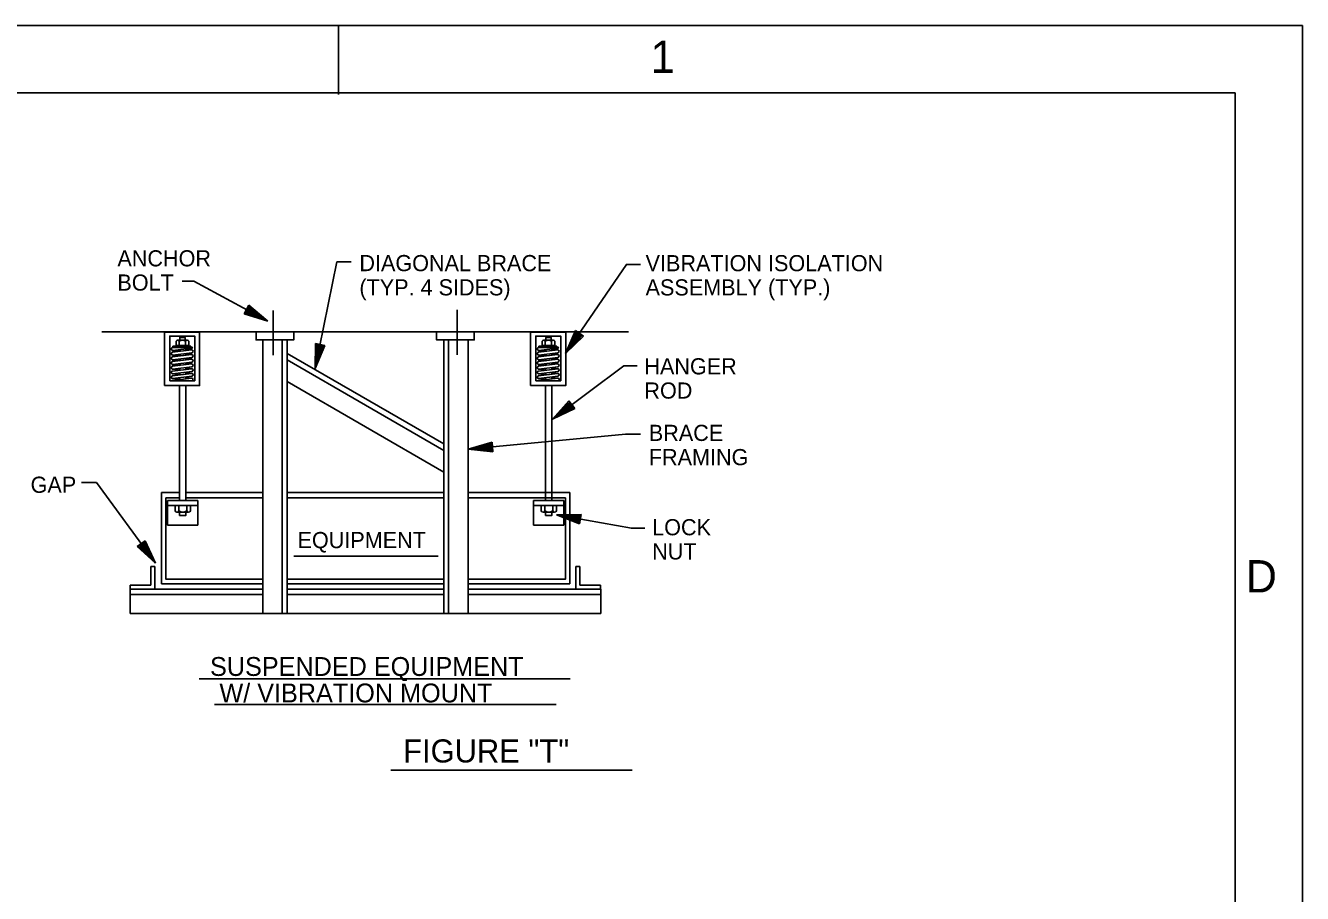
# Model space of a CAD drawing. Extents: x 9999.96 to 10005.26, y 9999.88 to 10002.38.
# Drawn here: x 10002.67 to 10003.46, y 10001.847 to 10002.385 of the extents above; entities that cross this region are included whole.
import ezdxf

# ---------------------------------------------------------------- set-up
doc = ezdxf.new("R2010")
doc.units = 0
doc.layers.add('Level 1', color=7, linetype='Continuous')
doc.layers.add('Level 2', color=7, linetype='Continuous')

msp = doc.modelspace()

# ---------------------------------------------------------------- linework, layer by layer
at = {"layer": 'Level 1'}
for p, q in [((9999.96033, 10002.38453), (10003.46033, 10002.38453)), ((10002.8635, 10002.38453), (10002.8635, 10002.34186)), ((10003.46033, 10002.38453), (10003.46033, 9999.88453)), ((10000.127, 10002.34286), (10003.41867, 10002.34286)), ((10003.41867, 10002.34286), (10003.41867, 9999.9262))]:
    msp.add_line(p, q, dxfattribs=at)
at = {"layer": 'Level 2'}
for p, q in [((10002.80502, 10002.20613), (10002.8079, 10002.21143)), ((10002.8197, 10002.20163), (10002.80577, 10002.20755)), ((10002.8197, 10002.20163), (10002.8061, 10002.20814)), ((10002.80643, 10002.20876), (10002.8197, 10002.20163)), ((10002.8197, 10002.20163), (10002.80679, 10002.20942)), ((10002.8197, 10002.20163), (10002.80714, 10002.21008)), ((10002.8197, 10002.20163), (10002.80749, 10002.21071)), ((10002.8079, 10002.21143), (10002.8197, 10002.20163)), ((10002.82292, 10002.18049), (10002.82292, 10002.20824)), ((10002.93701, 10002.18075), (10002.93701, 10002.2085)), ((10002.80502, 10002.20613), (10002.8197, 10002.20163)), ((10002.8197, 10002.20163), (10002.80539, 10002.2068)), ((10002.71686, 10002.19493), (10003.04293, 10002.19493)), ((10003.0101, 10002.19567), (10003.0041, 10002.18154)), ((10003.0041, 10002.18154), (10003.01074, 10002.19524)), ((10003.0041, 10002.18154), (10003.01145, 10002.19478)), ((10003.0041, 10002.18154), (10003.01199, 10002.19439)), ((10003.01257, 10002.194), (10003.0041, 10002.18154)), ((10003.0041, 10002.18154), (10003.0132, 10002.19356)), ((10003.0041, 10002.18154), (10003.01381, 10002.19316)), ((10003.0041, 10002.18154), (10003.01441, 10002.19274)), ((10003.01508, 10002.19226), (10003.0041, 10002.18154)), ((10003.0101, 10002.19567), (10003.01508, 10002.19226)), ((10002.76067, 10002.18524), (10002.77322, 10002.18524)), ((10002.76068, 10002.18232), (10002.77251, 10002.18378)), ((10002.76084, 10002.18346), (10002.77268, 10002.18491)), ((10002.77209, 10002.18606), (10002.76091, 10002.18606)), ((10002.76091, 10002.18606), (10002.76091, 10002.18524)), ((10002.76286, 10002.18642), (10002.76286, 10002.18917)), ((10002.76286, 10002.18642), (10002.77076, 10002.18642)), ((10002.76385, 10002.18976), (10002.76977, 10002.18976)), ((10002.76482, 10002.18642), (10002.76482, 10002.18917)), ((10002.76506, 10002.18398), (10002.76506, 10002.18288)), ((10002.76879, 10002.18642), (10002.76879, 10002.18917)), ((10002.76899, 10002.18446), (10002.76899, 10002.18333)), ((10002.76899, 10002.18423), (10002.77259, 10002.18379)), ((10002.77076, 10002.18642), (10002.77076, 10002.18915)), ((10002.77209, 10002.18606), (10002.77209, 10002.18524)), ((10002.81652, 10002.02061), (10002.81652, 10002.1899)), ((10002.82858, 10002.1899), (10002.82858, 10002.02061)), ((10002.83163, 10002.02061), (10002.83163, 10002.1899)), ((10002.84911, 10002.18763), (10002.84906, 10002.17227)), ((10002.84906, 10002.17227), (10002.84986, 10002.18747)), ((10002.84906, 10002.17227), (10002.8507, 10002.18732)), ((10002.84906, 10002.17227), (10002.85135, 10002.18717)), ((10002.85204, 10002.18704), (10002.84906, 10002.17227)), ((10002.84906, 10002.17227), (10002.85278, 10002.18688)), ((10002.84906, 10002.17227), (10002.85351, 10002.18674)), ((10002.84906, 10002.17227), (10002.85422, 10002.18658)), ((10002.85502, 10002.18642), (10002.84906, 10002.17227)), ((10002.84911, 10002.18763), (10002.85502, 10002.18642)), ((10002.92863, 10002.1899), (10002.92863, 10002.02061)), ((10002.93166, 10002.02061), (10002.93166, 10002.1899)), ((10002.94372, 10002.1899), (10002.94372, 10002.02061)), ((10002.98731, 10002.18524), (10002.99986, 10002.18524)), ((10002.98732, 10002.18232), (10002.99916, 10002.18378)), ((10002.98749, 10002.18346), (10002.99932, 10002.18491)), ((10002.99874, 10002.18606), (10002.98755, 10002.18606)), ((10002.98755, 10002.18606), (10002.98755, 10002.18524)), ((10002.98951, 10002.18642), (10002.98951, 10002.18917)), ((10002.98951, 10002.18642), (10002.99741, 10002.18642)), ((10002.9905, 10002.18976), (10002.99642, 10002.18976)), ((10002.99147, 10002.18642), (10002.99147, 10002.18917)), ((10002.99171, 10002.18398), (10002.99171, 10002.18288)), ((10002.99544, 10002.18642), (10002.99544, 10002.18917)), ((10002.99564, 10002.18446), (10002.99564, 10002.18333)), ((10002.99564, 10002.18423), (10002.99924, 10002.18379)), ((10002.99741, 10002.18642), (10002.99741, 10002.18915)), ((10002.99874, 10002.18606), (10002.99874, 10002.18524)), ((10002.76528, 10002.18289), (10002.76067, 10002.18346)), ((10002.76067, 10002.17942), (10002.7725, 10002.18086)), ((10002.76528, 10002.17706), (10002.76067, 10002.17764)), ((10002.76068, 10002.17651), (10002.77251, 10002.17795)), ((10002.76528, 10002.17999), (10002.76069, 10002.18053)), ((10002.76084, 10002.17765), (10002.77268, 10002.17908)), ((10002.76085, 10002.18054), (10002.77269, 10002.182)), ((10002.76085, 10002.17473), (10002.77269, 10002.17618)), ((10002.76506, 10002.18107), (10002.76506, 10002.17995)), ((10002.76506, 10002.17818), (10002.76506, 10002.17705)), ((10002.76899, 10002.18159), (10002.76899, 10002.18047)), ((10002.7727, 10002.18086), (10002.76899, 10002.18132)), ((10002.76899, 10002.17867), (10002.76899, 10002.1775)), ((10002.77268, 10002.17795), (10002.76899, 10002.17841)), ((10002.76899, 10002.17573), (10002.76899, 10002.1746)), ((10002.92863, 10002.1256), (10002.83163, 10002.1816)), ((10002.83163, 10002.17751), (10002.92863, 10002.12151)), ((10002.99193, 10002.18289), (10002.98731, 10002.18346)), ((10002.98731, 10002.17942), (10002.99915, 10002.18086)), ((10002.99193, 10002.17706), (10002.98731, 10002.17764)), ((10002.98732, 10002.17651), (10002.99916, 10002.17795)), ((10002.99193, 10002.17999), (10002.98733, 10002.18053)), ((10002.98749, 10002.17765), (10002.99932, 10002.17908)), ((10002.9875, 10002.18054), (10002.99933, 10002.182)), ((10002.9875, 10002.17473), (10002.99933, 10002.17618)), ((10002.99171, 10002.18107), (10002.99171, 10002.17995)), ((10002.99171, 10002.17818), (10002.99171, 10002.17705)), ((10002.99564, 10002.18159), (10002.99564, 10002.18047)), ((10002.99934, 10002.18086), (10002.99564, 10002.18132)), ((10002.99564, 10002.17867), (10002.99564, 10002.1775)), ((10002.99932, 10002.17795), (10002.99564, 10002.17841)), ((10002.99564, 10002.17573), (10002.99564, 10002.1746)), ((10002.76067, 10002.17359), (10002.7725, 10002.17504)), ((10002.76528, 10002.17124), (10002.76067, 10002.1718)), ((10002.76067, 10002.16777), (10002.7725, 10002.16921)), ((10002.76068, 10002.17068), (10002.77251, 10002.17213)), ((10002.76528, 10002.17416), (10002.76069, 10002.17472)), ((10002.76528, 10002.16833), (10002.76069, 10002.1689)), ((10002.76084, 10002.17181), (10002.77268, 10002.17326)), ((10002.76085, 10002.16891), (10002.77269, 10002.17035)), ((10002.76506, 10002.17528), (10002.76506, 10002.17413)), ((10002.76506, 10002.17239), (10002.76506, 10002.17123)), ((10002.76506, 10002.16946), (10002.76506, 10002.16832)), ((10002.7727, 10002.17504), (10002.76899, 10002.1755)), ((10002.76899, 10002.17283), (10002.76899, 10002.17171)), ((10002.77268, 10002.17213), (10002.76899, 10002.17258)), ((10002.76899, 10002.16991), (10002.76899, 10002.16878)), ((10002.7727, 10002.16921), (10002.76899, 10002.16968)), ((10002.98731, 10002.17359), (10002.99915, 10002.17504)), ((10002.99193, 10002.17124), (10002.98731, 10002.1718)), ((10002.98731, 10002.16777), (10002.99915, 10002.16921)), ((10002.98732, 10002.17068), (10002.99916, 10002.17213)), ((10002.99193, 10002.17416), (10002.98733, 10002.17472)), ((10002.99193, 10002.16833), (10002.98733, 10002.1689)), ((10002.98749, 10002.17181), (10002.99932, 10002.17326)), ((10002.9875, 10002.16891), (10002.99933, 10002.17035)), ((10002.99171, 10002.17528), (10002.99171, 10002.17413)), ((10002.99171, 10002.17239), (10002.99171, 10002.17123)), ((10002.99171, 10002.16946), (10002.99171, 10002.16832)), ((10002.99934, 10002.17504), (10002.99564, 10002.1755)), ((10002.99564, 10002.17283), (10002.99564, 10002.17171)), ((10002.99932, 10002.17213), (10002.99564, 10002.17258)), ((10002.99564, 10002.16991), (10002.99564, 10002.16878)), ((10002.99934, 10002.16921), (10002.99564, 10002.16968)), ((10002.75906, 10002.16466), (10002.77251, 10002.1663)), ((10002.76528, 10002.16542), (10002.76067, 10002.16598)), ((10002.76084, 10002.16599), (10002.77268, 10002.16743)), ((10002.76506, 10002.16652), (10002.76506, 10002.16536)), ((10002.76506, 10002.16164), (10002.76506, 10002.09052)), ((10002.76899, 10002.16701), (10002.76899, 10002.16585)), ((10002.77268, 10002.1663), (10002.76899, 10002.16675)), ((10002.76899, 10002.16156), (10002.76899, 10002.09052)), ((10002.92863, 10002.10817), (10002.83163, 10002.16417)), ((10002.98571, 10002.16466), (10002.99916, 10002.1663)), ((10002.99193, 10002.16542), (10002.98731, 10002.16598)), ((10002.98749, 10002.16599), (10002.99932, 10002.16743)), ((10002.99171, 10002.16652), (10002.99171, 10002.16536)), ((10002.99171, 10002.16164), (10002.99171, 10002.09052)), ((10002.99564, 10002.16701), (10002.99564, 10002.16585)), ((10002.99932, 10002.1663), (10002.99564, 10002.16675)), ((10002.99564, 10002.16156), (10002.99564, 10002.09052)), ((10003.00615, 10002.15224), (10002.99586, 10002.14084)), ((10003.00615, 10002.15224), (10003.00974, 10002.1474)), ((10002.99586, 10002.14084), (10003.0066, 10002.15163)), ((10002.99586, 10002.14084), (10003.00713, 10002.15096)), ((10002.99586, 10002.14084), (10003.00751, 10002.15042)), ((10003.00794, 10002.14985), (10002.99586, 10002.14084)), ((10002.99586, 10002.14084), (10003.00839, 10002.14924)), ((10002.99586, 10002.14084), (10003.00883, 10002.14866)), ((10002.99586, 10002.14084), (10003.00926, 10002.14806)), ((10003.00974, 10002.1474), (10002.99586, 10002.14084)), ((10002.95853, 10002.12672), (10002.94383, 10002.1223)), ((10002.94383, 10002.1223), (10002.9586, 10002.12596)), ((10002.94383, 10002.1223), (10002.95871, 10002.12511)), ((10002.94383, 10002.1223), (10002.95875, 10002.12445)), ((10002.95883, 10002.12375), (10002.94383, 10002.1223)), ((10002.94383, 10002.1223), (10002.95889, 10002.123)), ((10002.95909, 10002.12072), (10002.94383, 10002.1223)), ((10002.94383, 10002.1223), (10002.95897, 10002.12226)), ((10002.94383, 10002.1223), (10002.95903, 10002.12153)), ((10002.95853, 10002.12672), (10002.95909, 10002.12072)), ((10002.75383, 10002.09553), (10002.75383, 10002.03901)), ((10002.765, 10002.09553), (10002.75383, 10002.09553)), ((10002.7576, 10002.09051), (10002.77635, 10002.09051)), ((10002.7576, 10002.0753), (10002.7576, 10002.09051)), ((10002.81652, 10002.09553), (10002.76891, 10002.09553)), ((10002.77635, 10002.09051), (10002.77635, 10002.0753)), ((10002.92863, 10002.09553), (10002.83163, 10002.09553)), ((10002.92863, 10002.09218), (10002.83163, 10002.09218)), ((10003.00679, 10002.09553), (10002.94372, 10002.09553)), ((10002.99165, 10002.09553), (10002.98048, 10002.09553)), ((10002.98425, 10002.09051), (10003.003, 10002.09051)), ((10002.98425, 10002.0753), (10002.98425, 10002.09051)), ((10003.003, 10002.09051), (10003.003, 10002.0753)), ((10003.00679, 10002.03901), (10003.00679, 10002.09553)), ((10002.77635, 10002.08751), (10002.7576, 10002.08751)), ((10002.77181, 10002.08739), (10002.76226, 10002.08739)), ((10002.76226, 10002.08739), (10002.76226, 10002.08407)), ((10002.77061, 10002.08332), (10002.76345, 10002.08332)), ((10002.76465, 10002.08739), (10002.76465, 10002.08405)), ((10002.76945, 10002.08739), (10002.76945, 10002.08405)), ((10002.77181, 10002.08739), (10002.77181, 10002.08405)), ((10003.003, 10002.08751), (10002.98425, 10002.08751)), ((10002.99846, 10002.08739), (10002.98891, 10002.08739)), ((10002.98891, 10002.08739), (10002.98891, 10002.08407)), ((10002.99726, 10002.08332), (10002.99009, 10002.08332)), ((10002.99129, 10002.08739), (10002.99129, 10002.08405)), ((10002.99609, 10002.08739), (10002.99609, 10002.08405)), ((10003.01378, 10002.08193), (10002.99844, 10002.0816)), ((10003.01327, 10002.07899), (10002.99844, 10002.0816)), ((10003.01272, 10002.07599), (10002.99844, 10002.0816)), ((10002.99844, 10002.0816), (10003.01301, 10002.07751)), ((10002.99844, 10002.0816), (10003.01352, 10002.08033)), ((10002.99844, 10002.0816), (10003.01288, 10002.0768)), ((10002.99844, 10002.0816), (10003.01314, 10002.07825)), ((10002.99844, 10002.0816), (10003.01339, 10002.07969)), ((10002.99844, 10002.0816), (10003.01366, 10002.08117)), ((10002.99846, 10002.08739), (10002.99846, 10002.08405)), ((10003.01378, 10002.08193), (10003.01272, 10002.07599)), ((10002.77635, 10002.0753), (10002.7576, 10002.0753)), ((10003.003, 10002.0753), (10002.98425, 10002.0753)), ((10002.73884, 10002.0621), (10002.74371, 10002.06566)), ((10002.75016, 10002.05173), (10002.74304, 10002.06518)), ((10002.74371, 10002.06566), (10002.75016, 10002.05173)), ((10002.73884, 10002.0621), (10002.75016, 10002.05173)), ((10002.75016, 10002.05173), (10002.73946, 10002.06256)), ((10002.75016, 10002.05173), (10002.74013, 10002.06307)), ((10002.75016, 10002.05173), (10002.74068, 10002.06345)), ((10002.74124, 10002.06388), (10002.75016, 10002.05173)), ((10002.75016, 10002.05173), (10002.74185, 10002.06431)), ((10002.75016, 10002.05173), (10002.74245, 10002.06476)), ((10002.74723, 10002.03816), (10002.74723, 10002.04973)), ((10002.74723, 10002.04973), (10002.74982, 10002.04973)), ((10002.74982, 10002.04973), (10002.74982, 10002.03576)), ((10002.83579, 10002.05604), (10002.92509, 10002.05604)), ((10003.01298, 10002.04972), (10003.01038, 10002.04972)), ((10003.01038, 10002.04972), (10003.01038, 10002.03574)), ((10003.01298, 10002.03814), (10003.01298, 10002.04972)), ((10002.83163, 10002.0418), (10002.92863, 10002.0418)), ((10002.73444, 10002.03571), (10002.73444, 10002.03816)), ((10002.73444, 10002.03816), (10002.74723, 10002.03816)), ((10002.81652, 10002.03571), (10002.73444, 10002.03571)), ((10002.73444, 10002.02061), (10002.73444, 10002.03571)), ((10002.75383, 10002.03901), (10002.81652, 10002.03901)), ((10002.83163, 10002.03901), (10002.92863, 10002.03901)), ((10002.92863, 10002.03571), (10002.83164, 10002.03571)), ((10002.94371, 10002.03571), (10003.0258, 10002.03571)), ((10002.94372, 10002.03901), (10003.00679, 10002.03901)), ((10003.02577, 10002.03814), (10003.01298, 10002.03814)), ((10003.02577, 10002.03569), (10003.02577, 10002.03814)), ((10003.0258, 10002.02061), (10003.0258, 10002.03571)), ((10002.73444, 10002.03238), (10002.81655, 10002.03238)), ((10002.83158, 10002.03238), (10002.92855, 10002.03238)), ((10002.94369, 10002.03238), (10003.0258, 10002.03238)), ((10003.0258, 10002.02061), (10002.73444, 10002.02061)), ((10002.77721, 10001.98007), (10003.00689, 10001.98007)), ((10002.78676, 10001.96432), (10002.99829, 10001.96432)), ((10002.89585, 10001.92361), (10003.04531, 10001.92361))]:
    msp.add_line(p, q, dxfattribs=at)
for points in [[(10002.87121, 10002.2382), (10002.86245, 10002.2382), (10002.84906, 10002.17227)], [(10003.05047, 10002.23666), (10003.04171, 10002.23666), (10003.0041, 10002.18154)], [(10002.76664, 10002.22635), (10002.77385, 10002.22635), (10002.8197, 10002.20163)], [(10002.76844, 10002.18978), (10002.76844, 10002.19144), (10002.7652, 10002.19144), (10002.7652, 10002.18978)], [(10002.81241, 10002.19493), (10002.81241, 10002.1899), (10002.83574, 10002.1899), (10002.83574, 10002.19493)], [(10002.92419, 10002.19493), (10002.92419, 10002.1899), (10002.94752, 10002.1899), (10002.94752, 10002.19493)], [(10002.99508, 10002.18978), (10002.99508, 10002.19144), (10002.99184, 10002.19144), (10002.99184, 10002.18978)], [(10003.04841, 10002.17381), (10003.04017, 10002.17381), (10002.99586, 10002.14084)], [(10003.05047, 10002.13157), (10003.0412, 10002.13157), (10002.94383, 10002.1223)], [(10002.70431, 10002.1017), (10002.71358, 10002.1017), (10002.75016, 10002.05173)], [(10002.765, 10002.09218), (10002.75663, 10002.09218), (10002.75663, 10002.0418), (10002.81652, 10002.0418)], [(10002.81652, 10002.09218), (10002.76891, 10002.09218)], [(10002.94372, 10002.0418), (10003.00399, 10002.0418), (10003.00399, 10002.09218), (10002.94372, 10002.09218)], [(10002.76506, 10002.0833), (10002.76506, 10002.0813), (10002.76899, 10002.0813), (10002.76899, 10002.0833)], [(10002.99171, 10002.0833), (10002.99171, 10002.0813), (10002.99564, 10002.0813), (10002.99564, 10002.0833)], [(10003.05304, 10002.07336), (10003.0448, 10002.07336), (10002.99844, 10002.0816)]]:
    msp.add_lwpolyline(points, dxfattribs=at)
for points in [[(10002.75567, 10002.16164), (10002.77748, 10002.16164), (10002.77748, 10002.19482), (10002.75567, 10002.19482)], [(10002.75892, 10002.16466), (10002.77447, 10002.16466), (10002.77447, 10002.19227), (10002.75892, 10002.19227)], [(10002.98231, 10002.16164), (10003.00413, 10002.16164), (10003.00413, 10002.19482), (10002.98231, 10002.19482)], [(10002.98556, 10002.16466), (10003.00111, 10002.16466), (10003.00111, 10002.19227), (10002.98556, 10002.19227)]]:
    msp.add_lwpolyline(points, close=True, dxfattribs=at)
for centre, radius, start, end in [((10002.76385, 10002.18866), 0.0011, 27.8877, 152.03419), ((10002.76681, 10002.18611), 0.00365, 57.00616, 122.94298), ((10002.76977, 10002.18865), 0.0011, 26.78269, 151.8391), ((10002.99049, 10002.18866), 0.0011, 27.8877, 152.03419), ((10002.99345, 10002.18611), 0.00365, 57.00616, 122.94298), ((10002.99641, 10002.18865), 0.0011, 26.78269, 151.8391), ((10002.76346, 10002.08468), 0.00134, 206.78269, 331.8391), ((10002.76704, 10002.08774), 0.00441, 237.00616, 302.94298), ((10002.77062, 10002.08467), 0.00134, 207.8877, 332.03419), ((10002.9901, 10002.08468), 0.00134, 206.78269, 331.8391), ((10002.99369, 10002.08774), 0.00441, 237.00616, 302.94298), ((10002.99727, 10002.08467), 0.00134, 207.8877, 332.03419)]:
    msp.add_arc(centre, radius, start, end, dxfattribs=at)
for centre, major_axis, start_param, end_param in [((10002.76076, 10002.18434), (0, -0.000894), 3.251722, 6.393315), ((10002.77259, 10002.18289), (0, 0.000894), 3.251722, 6.393315), ((10002.77258, 10002.1858), (0, 0.000894), 3.251722, 4.030489), ((10002.9874, 10002.18434), (0, -0.000894), 3.251722, 6.393315), ((10002.99924, 10002.18289), (0, 0.000894), 3.251722, 6.393315), ((10002.99923, 10002.1858), (0, 0.000894), 3.251722, 4.030489), ((10002.76076, 10002.17852), (0, -0.000894), 3.251722, 6.393315), ((10002.76077, 10002.18143), (0, -0.000894), 3.251722, 6.393315), ((10002.76077, 10002.17561), (0, -0.000894), 3.251722, 6.393315), ((10002.77258, 10002.17997), (0, 0.000894), 3.251722, 6.393315), ((10002.77259, 10002.17706), (0, 0.000894), 3.251722, 6.393315), ((10002.9874, 10002.17852), (0, -0.000894), 3.251722, 6.393315), ((10002.98741, 10002.18143), (0, -0.000894), 3.251722, 6.393315), ((10002.98741, 10002.17561), (0, -0.000894), 3.251722, 6.393315), ((10002.99923, 10002.17997), (0, 0.000894), 3.251722, 6.393315), ((10002.99924, 10002.17706), (0, 0.000894), 3.251722, 6.393315), ((10002.76076, 10002.1727), (0, -0.000894), 3.251722, 6.393315), ((10002.76076, 10002.16687), (0, -0.000894), 3.251722, 6.393315), ((10002.76077, 10002.16979), (0, -0.000894), 3.251722, 6.393315), ((10002.77258, 10002.17415), (0, 0.000894), 3.251722, 6.393315), ((10002.77258, 10002.16833), (0, 0.000894), 3.251722, 6.393315), ((10002.77259, 10002.17124), (0, 0.000894), 3.251722, 6.393315), ((10002.9874, 10002.1727), (0, -0.000894), 3.251722, 6.393315), ((10002.9874, 10002.16687), (0, -0.000894), 3.251722, 6.393315), ((10002.98741, 10002.16979), (0, -0.000894), 3.251722, 6.393315), ((10002.99923, 10002.17415), (0, 0.000894), 3.251722, 6.393315), ((10002.99923, 10002.16833), (0, 0.000894), 3.251722, 6.393315), ((10002.99924, 10002.17124), (0, 0.000894), 3.251722, 6.393315), ((10002.77259, 10002.16542), (0, 0.000894), 3.693893, 6.387949), ((10002.99924, 10002.16542), (0, 0.000894), 3.693893, 6.387949)]:
    msp.add_ellipse(centre, major_axis=major_axis, ratio=0.9, start_param=start_param, end_param=end_param, dxfattribs=at)

# ---------------------------------------------------------------- texts
at = {"layer": 'Level 1'}
for s, p in [('1', (10003.05675, 10002.3552)), ('D', (10003.42519, 10002.03363))]:
    msp.add_text(s, height=0.02, dxfattribs=at).set_placement(p)
at = {"layer": 'Level 2'}
for s, height, p in [('ANCHOR', 0.01, (10002.72654, 10002.23545)), ('DIAGONAL BRACE', 0.01, (10002.87638, 10002.23249)), ('VIBRATION ISOLATION', 0.01, (10003.0536, 10002.23245)), ('BOLT', 0.01, (10002.72654, 10002.22045)), ('(TYP. 4 SIDES)', 0.01, (10002.87638, 10002.21749)), ('ASSEMBLY (TYP.)', 0.01, (10003.0536, 10002.21745)), ('HANGER', 0.01, (10003.05285, 10002.1686)), ('ROD', 0.01, (10003.05285, 10002.1536)), ('BRACE', 0.01, (10003.0556, 10002.12739)), ('FRAMING', 0.01, (10003.0556, 10002.11239)), ('GAP', 0.01, (10002.6728, 10002.09529)), ('LOCK', 0.01, (10003.05767, 10002.069)), ('EQUIPMENT', 0.01, (10002.83808, 10002.06104)), ('NUT', 0.01, (10003.05767, 10002.054)), ('SUSPENDED EQUIPMENT', 0.0116667, (10002.7839, 10001.98195)), ('W/ VIBRATION MOUNT', 0.0116667, (10002.78974, 10001.96557)), ('FIGURE "T"', 0.014301, (10002.90348, 10001.92835))]:
    msp.add_text(s, height=height, dxfattribs=at).set_placement(p)

doc.saveas('drawing.dxf')
